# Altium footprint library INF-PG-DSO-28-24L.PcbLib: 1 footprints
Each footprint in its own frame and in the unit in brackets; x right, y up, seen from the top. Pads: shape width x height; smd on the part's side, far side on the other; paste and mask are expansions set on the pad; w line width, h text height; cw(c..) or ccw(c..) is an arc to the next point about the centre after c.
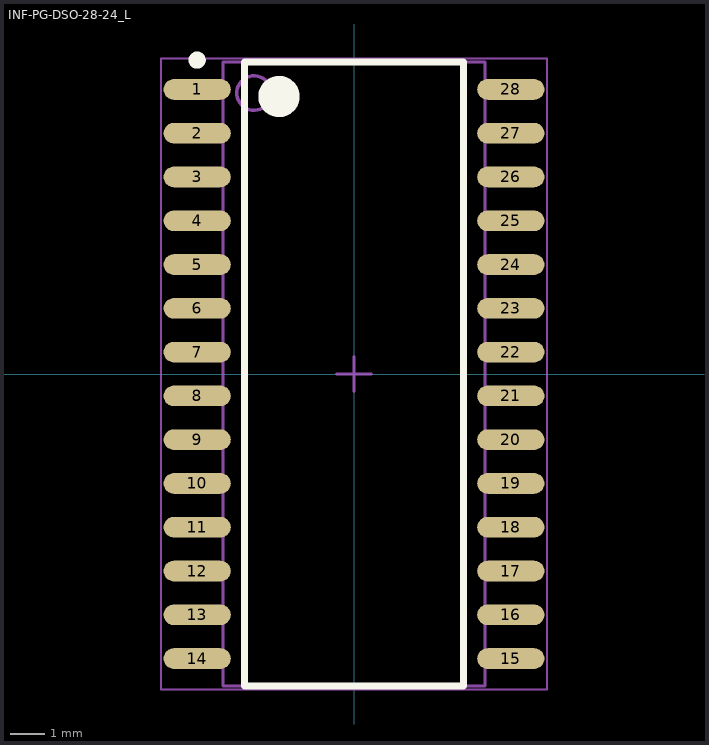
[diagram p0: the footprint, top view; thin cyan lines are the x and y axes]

## INF-PG-DSO-28-24_L [mm] "SOP, 28-Leads, Body 17.9x7.5mm, Pitch 1.27mm, IPC High Density"
height 2.65
pads (28):
  oval 1.95x0.6 smd: 1(-4.55,8.255) 2(-4.55,6.985) 3(-4.55,5.715) 4(-4.55,4.445) 5(-4.55,3.175) 6(-4.55,1.905) 7(-4.55,0.635) 8(-4.55,-0.635) 9(-4.55,-1.905) 10(-4.55,-3.175) 11(-4.55,-4.445) 12(-4.55,-5.715) 13(-4.55,-6.985) 14(-4.55,-8.255) 15(4.55,-8.255) 16(4.55,-6.985) 17(4.55,-5.715) 18(4.55,-4.445) 19(4.55,-3.175) 20(4.55,-1.905) 21(4.55,-0.635) 22(4.55,0.635) 23(4.55,1.905) 24(4.55,3.175) 25(4.55,4.445) 26(4.55,5.715) 27(4.55,6.985) 28(4.55,8.255)
Top Overlay:
  circle w0.6: c-2.175,8.05 r0.3
  circle w0.25: c-4.55,9.105 r0.125
  lines w0.2: -3.175,-9.05 3.175,-9.05 3.175,9.05 -3.175,9.05 -3.175,-9.05
Mechanical 13:
  circle w0.1: c-2.9,8.15 r0.5
  lines w0.1: -3.8,-9.05 3.8,-9.05 3.8,9.05 -3.8,9.05 -3.8,-9.05
Mechanical 15:
  lines w0.05: -5.6,-9.15 5.6,-9.15 5.6,9.15 -5.6,9.15 -5.6,-9.15
  lines w0.1: -0.5,0 0.5,0 ; 0,-0.5 0,0.5
3D body: height 2.65, standoff 0.1, extent -3.8,-9.05 3.8,9.05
